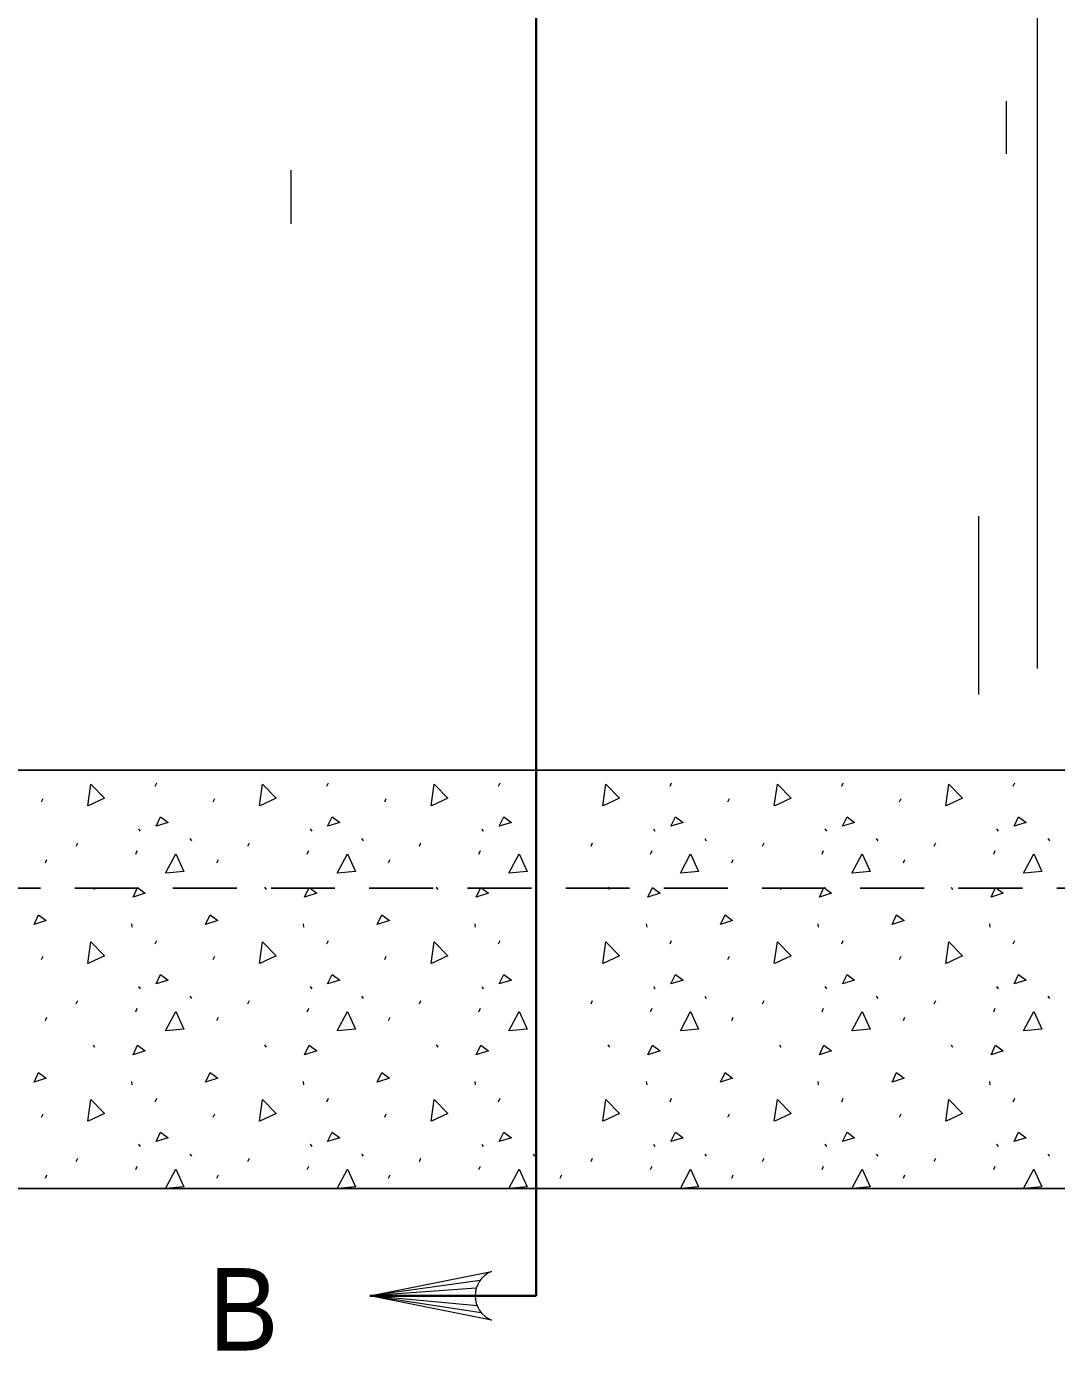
# Model space of a CAD drawing. Extents: x 1302.9 to 1336.9, y 688.5 to 710.5.
# Drawn here: x 1308.457 to 1311.457, y 691.519 to 695.374 of the extents above; entities that cross this region are included whole.
import ezdxf

# ---------------------------------------------------------------- set-up
doc = ezdxf.new("R2010")
doc.units = 0
doc.header["$LTSCALE"] = 0.062
doc.linetypes.add('MEDIUM_DASHED', pattern=[4.5, 3, -1.5])
doc.layers.add('1', color=7, linetype='Continuous', lineweight=13)

msp = doc.modelspace()

# ---------------------------------------------------------------- linework, layer by layer
at = {"layer": '1', "lineweight": 35}
for p, q in [((1309.9415, 692.06492), (1309.9415, 702.87)), ((1309.94142, 691.678), (1309.94142, 692.06492)), ((1309.94142, 691.678), (1309.45733, 691.678))]:
    msp.add_line(p, q, dxfattribs=at)
at = {"layer": '1'}
for p, q in [((1311.40092, 693.50458), (1311.40092, 696.44417)), ((1311.31, 695.157), (1311.31, 695.00358)), ((1309.22675, 694.956), (1309.22675, 694.79892)), ((1311.22983, 693.94783), (1311.22983, 693.42917)), ((1308.832, 693.16158), (1308.83642, 693.17158)), ((1309.33175, 693.16158), (1309.33617, 693.17158)), ((1309.83158, 693.16158), (1309.836, 693.17158)), ((1310.33133, 693.16158), (1310.33575, 693.17158)), ((1310.83108, 693.16158), (1310.8355, 693.17158)), ((1311.33083, 693.16158), (1311.33525, 693.17158)), ((1308.50083, 693.11608), (1308.50533, 693.12608)), ((1309.00058, 693.11608), (1309.00508, 693.12608)), ((1309.50033, 693.11608), (1309.50483, 693.12608)), ((1310.49992, 693.11608), (1310.50442, 693.12608)), ((1310.99967, 693.11608), (1311.00417, 693.12608)), ((1308.78333, 693.03733), (1308.78775, 693.03075)), ((1308.93283, 693.00917), (1308.93725, 693.0025)), ((1309.28308, 693.03733), (1309.28758, 693.03075)), ((1309.43258, 693.00917), (1309.437, 693.0025)), ((1309.78283, 693.03733), (1309.78733, 693.03075)), ((1310.28258, 693.03733), (1310.28708, 693.03075)), ((1310.43208, 693.00917), (1310.4365, 693.0025)), ((1310.78233, 693.03733), (1310.78683, 693.03075)), ((1310.93183, 693.00917), (1310.93625, 693.0025)), ((1311.28208, 693.03733), (1311.28658, 693.03075)), ((1311.43167, 693.00917), (1311.43608, 693.0025)), ((1308.60192, 692.98742), (1308.60633, 692.99742)), ((1308.775, 692.96425), (1308.77942, 692.97425)), ((1309.10167, 692.98742), (1309.10608, 692.99742)), ((1309.27475, 692.96425), (1309.27917, 692.97425)), ((1309.60142, 692.98742), (1309.60583, 692.99742)), ((1309.7745, 692.96425), (1309.77892, 692.97425)), ((1310.10117, 692.98742), (1310.10558, 692.99742)), ((1310.27425, 692.96425), (1310.27867, 692.97425)), ((1310.60092, 692.98742), (1310.60533, 692.99742)), ((1310.774, 692.96425), (1310.77842, 692.97425)), ((1311.10067, 692.98742), (1311.10508, 692.99742)), ((1311.27375, 692.96425), (1311.27817, 692.97425)), ((1308.512, 692.93875), (1308.51642, 692.94867)), ((1309.01175, 692.93875), (1309.01617, 692.94867)), ((1309.5115, 692.93875), (1309.51592, 692.94867)), ((1310.51108, 692.93875), (1310.5155, 692.94867)), ((1311.01083, 692.93875), (1311.01525, 692.94867)), ((1308.65067, 692.86775), (1308.65508, 692.86108)), ((1309.15042, 692.86775), (1309.15483, 692.86108)), ((1309.65025, 692.86775), (1309.65467, 692.86108)), ((1310.15, 692.86775), (1310.15442, 692.86108)), ((1310.64975, 692.86775), (1310.65417, 692.86108)), ((1311.1495, 692.86775), (1311.15392, 692.86108)), ((1308.76283, 692.76125), (1308.764, 692.75125)), ((1309.26258, 692.76125), (1309.26375, 692.75125)), ((1309.76233, 692.76125), (1309.7635, 692.75125)), ((1310.26208, 692.76125), (1310.26325, 692.75125)), ((1310.76183, 692.76125), (1310.763, 692.75125)), ((1311.26167, 692.76125), (1311.26283, 692.75125)), ((1308.832, 692.70242), (1308.83642, 692.71242)), ((1309.33175, 692.70242), (1309.33617, 692.71242)), ((1309.83158, 692.70242), (1309.836, 692.71242)), ((1310.33133, 692.70242), (1310.33575, 692.71242)), ((1310.83108, 692.70242), (1310.8355, 692.71242)), ((1311.33083, 692.70242), (1311.33525, 692.71242)), ((1308.50083, 692.65692), (1308.50533, 692.66692)), ((1309.00058, 692.65692), (1309.00508, 692.66692)), ((1309.50033, 692.65692), (1309.50483, 692.66692)), ((1310.49992, 692.65692), (1310.50442, 692.66692)), ((1310.99967, 692.65692), (1311.00417, 692.66692)), ((1308.78333, 692.57825), (1308.78775, 692.57158)), ((1308.93283, 692.55), (1308.93725, 692.54333)), ((1309.28308, 692.57825), (1309.28758, 692.57158)), ((1309.43258, 692.55), (1309.437, 692.54333)), ((1309.78283, 692.57825), (1309.78733, 692.57158)), ((1310.28258, 692.57825), (1310.28708, 692.57158)), ((1310.43208, 692.55), (1310.4365, 692.54333)), ((1310.78233, 692.57825), (1310.78683, 692.57158)), ((1310.93183, 692.55), (1310.93625, 692.54333)), ((1311.28208, 692.57825), (1311.28658, 692.57158)), ((1311.43167, 692.55), (1311.43608, 692.54333)), ((1308.60192, 692.52825), (1308.60633, 692.53825)), ((1308.775, 692.50508), (1308.77942, 692.51508)), ((1309.10167, 692.52825), (1309.10608, 692.53825)), ((1309.27475, 692.50508), (1309.27917, 692.51508)), ((1309.60142, 692.52825), (1309.60583, 692.53825)), ((1309.7745, 692.50508), (1309.77892, 692.51508)), ((1310.10117, 692.52825), (1310.10558, 692.53825)), ((1310.27425, 692.50508), (1310.27867, 692.51508)), ((1310.60092, 692.52825), (1310.60533, 692.53825)), ((1310.774, 692.50508), (1310.77842, 692.51508)), ((1311.10067, 692.52825), (1311.10508, 692.53825)), ((1311.27375, 692.50508), (1311.27817, 692.51508)), ((1308.512, 692.47958), (1308.51642, 692.4895)), ((1309.01175, 692.47958), (1309.01617, 692.4895)), ((1309.5115, 692.47958), (1309.51592, 692.4895)), ((1310.51108, 692.47958), (1310.5155, 692.4895)), ((1311.01083, 692.47958), (1311.01525, 692.4895)), ((1308.65067, 692.40858), (1308.65508, 692.40192)), ((1309.15042, 692.40858), (1309.15483, 692.40192)), ((1309.65025, 692.40858), (1309.65467, 692.40192)), ((1310.15, 692.40858), (1310.15442, 692.40192)), ((1310.64975, 692.40858), (1310.65417, 692.40192)), ((1311.1495, 692.40858), (1311.15392, 692.40192)), ((1308.76283, 692.30217), (1308.764, 692.29217)), ((1309.26258, 692.30217), (1309.26375, 692.29217)), ((1309.76233, 692.30217), (1309.7635, 692.29217)), ((1310.26208, 692.30217), (1310.26325, 692.29217)), ((1310.76183, 692.30217), (1310.763, 692.29217)), ((1311.26167, 692.30217), (1311.26283, 692.29217)), ((1308.832, 692.24325), (1308.83642, 692.25325)), ((1309.33175, 692.24325), (1309.33617, 692.25325)), ((1309.83158, 692.24325), (1309.836, 692.25325)), ((1310.33133, 692.24325), (1310.33575, 692.25325)), ((1310.83108, 692.24325), (1310.8355, 692.25325)), ((1311.33083, 692.24325), (1311.33525, 692.25325)), ((1308.50083, 692.19775), (1308.50533, 692.20775)), ((1309.00058, 692.19775), (1309.00508, 692.20775)), ((1309.50033, 692.19775), (1309.50483, 692.20775)), ((1310.49992, 692.19775), (1310.50442, 692.20775)), ((1310.99967, 692.19775), (1311.00417, 692.20775)), ((1308.78333, 692.11908), (1308.78775, 692.11242)), ((1309.28308, 692.11908), (1309.28758, 692.11242)), ((1309.78283, 692.11908), (1309.78733, 692.11242)), ((1310.28258, 692.11908), (1310.28708, 692.11242)), ((1310.78233, 692.11908), (1310.78683, 692.11242)), ((1311.28208, 692.11908), (1311.28658, 692.11242)), ((1308.60192, 692.06908), (1308.60633, 692.07908)), ((1308.93283, 692.09083), (1308.93725, 692.08417)), ((1309.10167, 692.06908), (1309.10608, 692.07908)), ((1309.43258, 692.09083), (1309.437, 692.08417)), ((1309.60142, 692.06908), (1309.60583, 692.07908)), ((1309.93233, 692.09083), (1309.93675, 692.08417)), ((1310.10117, 692.06908), (1310.10558, 692.07908)), ((1310.43208, 692.09083), (1310.4365, 692.08417)), ((1310.60092, 692.06908), (1310.60533, 692.07908)), ((1310.93183, 692.09083), (1310.93625, 692.08417)), ((1311.10067, 692.06908), (1311.10508, 692.07908)), ((1311.43167, 692.09083), (1311.43608, 692.08417)), ((1308.775, 692.04592), (1308.77942, 692.05592)), ((1309.27475, 692.04592), (1309.27917, 692.05592)), ((1309.7745, 692.04592), (1309.77892, 692.05592)), ((1310.27425, 692.04592), (1310.27867, 692.05592)), ((1310.774, 692.04592), (1310.77842, 692.05592)), ((1311.27375, 692.04592), (1311.27817, 692.05592)), ((1308.512, 692.02042), (1308.51642, 692.03033)), ((1309.01175, 692.02042), (1309.01617, 692.03033)), ((1309.5115, 692.02042), (1309.51592, 692.03033)), ((1310.01133, 692.02042), (1310.01575, 692.03033)), ((1310.51108, 692.02042), (1310.5155, 692.03033)), ((1311.01083, 692.02042), (1311.01525, 692.03033)), ((1309.77783, 691.72283), (1309.45733, 691.678)), ((1309.76692, 691.70067), (1309.45733, 691.678)), ((1309.76367, 691.678), (1309.45733, 691.678)), ((1309.76933, 691.64917), (1309.45733, 691.678)), ((1309.78158, 691.62842), (1309.45733, 691.678))]:
    msp.add_line(p, q, dxfattribs=at)
at = {"layer": '1', "lineweight": 25}
msp.add_line((1312.14367, 693.20833), (1307.73933, 693.20833), dxfattribs=at)
at = {"layer": '1', "linetype": 'MEDIUM_DASHED', "lineweight": 25}
msp.add_line((1307.73933, 692.86483), (1312.14367, 692.86483), dxfattribs=at)
at = {"layer": '1', "lineweight": 25}
msp.add_lwpolyline([(1306.08392, 691.99033), (1313.799, 691.99033), (1313.799, 693.20833), (1312.58092, 693.20833)], dxfattribs=at)
at = {"layer": '1'}
for points in [[(1308.63583, 693.10458), (1308.64467, 693.16808), (1308.68442, 693.127), (1308.63683, 693.105)], [(1309.13567, 693.10458), (1309.14442, 693.16808), (1309.18417, 693.127), (1309.13667, 693.105)], [(1309.63542, 693.10458), (1309.64425, 693.16808), (1309.68392, 693.127), (1309.63642, 693.105)], [(1310.13517, 693.10458), (1310.144, 693.16808), (1310.18375, 693.127), (1310.13617, 693.105)], [(1310.63492, 693.10458), (1310.64375, 693.16808), (1310.6835, 693.127), (1310.63592, 693.105)], [(1311.13467, 693.10458), (1311.1435, 693.16808), (1311.18325, 693.127), (1311.13567, 693.105)], [(1308.86192, 692.90875), (1308.89192, 692.96533), (1308.91525, 692.91317), (1308.86308, 692.90875)], [(1309.36167, 692.90875), (1309.39167, 692.96533), (1309.415, 692.91317), (1309.36283, 692.90875)], [(1309.86142, 692.90875), (1309.89142, 692.96533), (1309.91475, 692.91317), (1309.86258, 692.90875)], [(1310.36125, 692.90875), (1310.39117, 692.96533), (1310.4145, 692.91317), (1310.36242, 692.90875)], [(1310.861, 692.90875), (1310.891, 692.96533), (1310.91433, 692.91317), (1310.86217, 692.90875)], [(1311.36075, 692.90875), (1311.39075, 692.96533), (1311.41408, 692.91317), (1311.36192, 692.90875)], [(1308.63583, 692.64542), (1308.64467, 692.70892), (1308.68442, 692.66783), (1308.63683, 692.64583)], [(1309.13567, 692.64542), (1309.14442, 692.70892), (1309.18417, 692.66783), (1309.13667, 692.64583)], [(1309.63542, 692.64542), (1309.64425, 692.70892), (1309.68392, 692.66783), (1309.63642, 692.64583)], [(1310.13517, 692.64542), (1310.144, 692.70892), (1310.18375, 692.66783), (1310.13617, 692.64583)], [(1310.63492, 692.64542), (1310.64375, 692.70892), (1310.6835, 692.66783), (1310.63592, 692.64583)], [(1311.13467, 692.64542), (1311.1435, 692.70892), (1311.18325, 692.66783), (1311.13567, 692.64583)], [(1308.86192, 692.44967), (1308.89192, 692.50617), (1308.91525, 692.454), (1308.86308, 692.44967)], [(1309.36167, 692.44967), (1309.39167, 692.50617), (1309.415, 692.454), (1309.36283, 692.44967)], [(1309.86142, 692.44967), (1309.89142, 692.50617), (1309.91475, 692.454), (1309.86258, 692.44967)], [(1310.36125, 692.44967), (1310.39117, 692.50617), (1310.4145, 692.454), (1310.36242, 692.44967)], [(1310.861, 692.44967), (1310.891, 692.50617), (1310.91433, 692.454), (1310.86217, 692.44967)], [(1311.36075, 692.44967), (1311.39075, 692.50617), (1311.41408, 692.454), (1311.36192, 692.44967)], [(1308.63583, 692.18625), (1308.64467, 692.24975), (1308.68442, 692.20867), (1308.63683, 692.18667)], [(1309.13567, 692.18625), (1309.14442, 692.24975), (1309.18417, 692.20867), (1309.13667, 692.18667)], [(1309.63542, 692.18625), (1309.64425, 692.24975), (1309.68392, 692.20867), (1309.63642, 692.18667)], [(1310.13517, 692.18625), (1310.144, 692.24975), (1310.18375, 692.20867), (1310.13617, 692.18667)], [(1310.63492, 692.18625), (1310.64375, 692.24975), (1310.6835, 692.20867), (1310.63592, 692.18667)], [(1311.13467, 692.18625), (1311.1435, 692.24975), (1311.18325, 692.20867), (1311.13567, 692.18667)], [(1308.86192, 691.9905), (1308.89192, 692.047), (1308.91525, 691.99492), (1308.86308, 691.9905)], [(1309.36167, 691.9905), (1309.39167, 692.047), (1309.415, 691.99492), (1309.36283, 691.9905)], [(1309.86142, 691.9905), (1309.89142, 692.047), (1309.91475, 691.99492), (1309.86258, 691.9905)], [(1310.36125, 691.9905), (1310.39117, 692.047), (1310.4145, 691.99492), (1310.36242, 691.9905)], [(1310.861, 691.9905), (1310.891, 692.047), (1310.91433, 691.99492), (1310.86217, 691.9905)], [(1311.36075, 691.9905), (1311.39075, 692.047), (1311.41408, 691.99492), (1311.36192, 691.9905)], [(1309.81133, 691.60717), (1309.45733, 691.678), (1309.81133, 691.74875)]]:
    msp.add_lwpolyline(points, dxfattribs=at)
for points in [[(1308.83417, 693.04508), (1308.8475, 693.07283), (1308.86975, 693.05617)], [(1309.33392, 693.04508), (1309.34725, 693.07283), (1309.3695, 693.05617)], [(1309.83375, 693.04508), (1309.84708, 693.07283), (1309.86925, 693.05617)], [(1310.3335, 693.04508), (1310.34683, 693.07283), (1310.36908, 693.05617)], [(1310.83325, 693.04508), (1310.84658, 693.07283), (1310.86883, 693.05617)], [(1311.333, 693.04508), (1311.34633, 693.07283), (1311.36858, 693.05617)], [(1308.76717, 692.83892), (1308.7805, 692.86667), (1308.80267, 692.85)], [(1309.26692, 692.83892), (1309.28025, 692.86667), (1309.3025, 692.85)], [(1309.76667, 692.83892), (1309.78, 692.86667), (1309.80225, 692.85)], [(1310.26642, 692.83892), (1310.27975, 692.86667), (1310.302, 692.85)], [(1310.76617, 692.83892), (1310.7795, 692.86667), (1310.80175, 692.85)], [(1311.266, 692.83892), (1311.27925, 692.86667), (1311.3015, 692.85)], [(1308.47892, 692.7595), (1308.49225, 692.78733), (1308.51442, 692.77067)], [(1308.97867, 692.7595), (1308.992, 692.78733), (1309.01417, 692.77067)], [(1309.4785, 692.7595), (1309.49183, 692.78733), (1309.51392, 692.77067)], [(1310.478, 692.7595), (1310.49133, 692.78733), (1310.5135, 692.77067)], [(1310.97775, 692.7595), (1310.99108, 692.78733), (1311.01325, 692.77067)], [(1308.83417, 692.586), (1308.8475, 692.61367), (1308.86975, 692.597)], [(1309.33392, 692.586), (1309.34725, 692.61367), (1309.3695, 692.597)], [(1309.83375, 692.586), (1309.84708, 692.61367), (1309.86925, 692.597)], [(1310.3335, 692.586), (1310.34683, 692.61367), (1310.36908, 692.597)], [(1310.83325, 692.586), (1310.84658, 692.61367), (1310.86883, 692.597)], [(1311.333, 692.586), (1311.34633, 692.61367), (1311.36858, 692.597)], [(1308.76717, 692.37975), (1308.7805, 692.4075), (1308.80267, 692.39083)], [(1309.26692, 692.37975), (1309.28025, 692.4075), (1309.3025, 692.39083)], [(1309.76667, 692.37975), (1309.78, 692.4075), (1309.80225, 692.39083)], [(1310.26642, 692.37975), (1310.27975, 692.4075), (1310.302, 692.39083)], [(1310.76617, 692.37975), (1310.7795, 692.4075), (1310.80175, 692.39083)], [(1311.266, 692.37975), (1311.27925, 692.4075), (1311.3015, 692.39083)], [(1308.47892, 692.3005), (1308.49225, 692.32817), (1308.51442, 692.3115)], [(1308.97867, 692.3005), (1308.992, 692.32817), (1309.01417, 692.3115)], [(1309.4785, 692.3005), (1309.49183, 692.32817), (1309.51392, 692.3115)], [(1310.478, 692.3005), (1310.49133, 692.32817), (1310.5135, 692.3115)], [(1310.97775, 692.3005), (1310.99108, 692.32817), (1311.01325, 692.3115)], [(1308.83417, 692.12683), (1308.8475, 692.15458), (1308.86975, 692.13792)], [(1309.33392, 692.12683), (1309.34725, 692.15458), (1309.3695, 692.13792)], [(1309.83375, 692.12683), (1309.84708, 692.15458), (1309.86925, 692.13792)], [(1310.3335, 692.12683), (1310.34683, 692.15458), (1310.36908, 692.13792)], [(1310.83325, 692.12683), (1310.84658, 692.15458), (1310.86883, 692.13792)], [(1311.333, 692.12683), (1311.34633, 692.15458), (1311.36858, 692.13792)]]:
    msp.add_lwpolyline(points, close=True, dxfattribs=at)
msp.add_arc((1309.8399, 691.67807), 0.0764, 112.08782, 247.91395, dxfattribs=at)

# ---------------------------------------------------------------- texts
at = {"layer": '1', "width": 0.95}
msp.add_text('B', height=0.24, dxfattribs=at).set_placement((1308.98758, 691.51867))

doc.saveas('drawing.dxf')
